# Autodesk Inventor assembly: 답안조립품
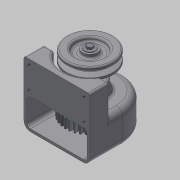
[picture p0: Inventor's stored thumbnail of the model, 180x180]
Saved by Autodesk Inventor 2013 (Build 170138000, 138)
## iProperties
Created: 2015-02
Part Number: 답안조립품
Document SubType Name: Assembly
Designer: Administrator
Author: Administrator
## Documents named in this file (14)
- C:\Users\Administrator\Desktop\450216V1011\답안조립품.iam
- C:\Users\Administrator\Desktop\450216V1011\본체.ipt
- C:\Users\Administrator\Desktop\450216V1011\베어링 6001.ipt
- C:\Users\Administrator\Desktop\450216V1011\축.ipt
- C:\Users\Administrator\Desktop\450216V1011\키5x5.ipt
- C:\Users\Administrator\Desktop\450216V1011\스퍼기어.ipt
- C:\Users\Administrator\Desktop\450216V1011\축커버.ipt
- C:\Users\Administrator\Desktop\450216V1011\오일실.ipt
- C:\Users\Administrator\Desktop\450216V1011\M3x0.5.ipt
- C:\Users\Administrator\Desktop\450216V1011\키4x4.ipt
- C:\Users\Administrator\Desktop\450216V1011\V-벨트풀리.ipt
- C:\Users\Administrator\Desktop\450216V1011\와샤.ipt
- C:\Users\Administrator\Desktop\450216V1011\M5x0.8.ipt
- M5x0.8.ipt
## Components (6 placed, 3 different names)
1. V-벨트풀리:1 — 각도:2
2. M5x0.8:1
3. M3x0.5:1
4. M3x0.5:2
5. M3x0.5:3
6. M3x0.5:4
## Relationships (1: Angle 1)
- 각도:2 [Angle]: V-벨트풀리:1
